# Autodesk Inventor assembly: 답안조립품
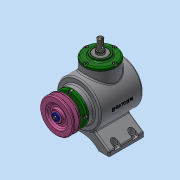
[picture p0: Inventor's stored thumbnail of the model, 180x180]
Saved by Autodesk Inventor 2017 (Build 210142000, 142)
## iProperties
Part Number: 답안조립품
Material: 일반
Document SubType Name: Assembly
Designer: MRC
Author: MRC
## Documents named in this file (17)
- C:\Users\MRC\Desktop\730108V1008\답안조립품.iam
- C:\Users\MRC\Desktop\730108V1008\본체.ipt
- C:\Users\MRC\Desktop\730108V1008\V-벨트풀리.ipt
- C:\Users\MRC\Desktop\730108V1008\메인 베벨기어.ipt
- C:\Users\MRC\Desktop\730108V1008\메인 축.ipt
- 메인 축.ipt
- C:\Users\MRC\Desktop\730108V1008\베어링 6203.ipt
- C:\Users\MRC\Desktop\730108V1008\볼트 M4 x 10.ipt
- C:\Users\MRC\Desktop\730108V1008\서브 베벨기어.ipt
- C:\Users\MRC\Desktop\730108V1008\서브 축.ipt
- 서브 축.ipt
- C:\Users\MRC\Desktop\730108V1008\오일실 17 x 32 x 8.ipt
- C:\Users\MRC\Desktop\730108V1008\와셔 4 x 16.ipt
- C:\Users\MRC\Desktop\730108V1008\육각볼트 M4 x 8.ipt
- C:\Users\MRC\Desktop\730108V1008\커버.ipt
- C:\Users\MRC\Desktop\730108V1008\키 4 x 4 x 14.ipt
- C:\Users\MRC\Desktop\730108V1008\키 5 x 5 x 14.ipt
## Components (1 placed, 1 different names)
1. V-벨트풀리:1
